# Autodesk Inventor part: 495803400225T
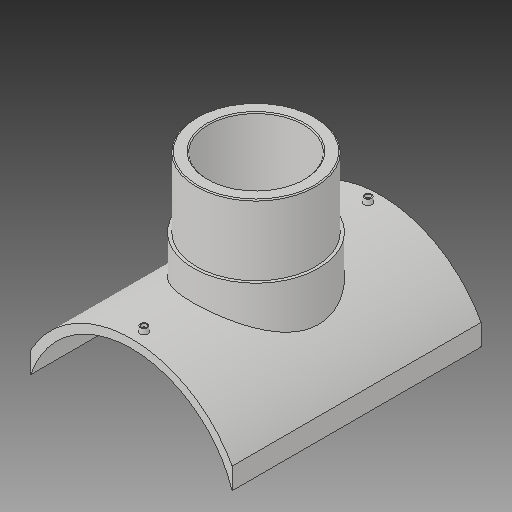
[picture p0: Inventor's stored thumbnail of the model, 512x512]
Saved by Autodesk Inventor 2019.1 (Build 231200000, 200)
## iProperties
Created: 2017-10
Part Number: 495803400225T
Material: Generic
Description: PLASSON BRANCH SADDLE  400x225
Document SubType Name: Modeling
Designer: KIM
Mass: 2754.05 g
Surface Area: 3037.44 cm^2
Volume: 2754.05 cm^3
Density: 1 g/cm^3
Appearance: Default
Author: KIM
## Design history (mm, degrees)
derived "495803.ipt"
feature "Solid1::495803.ipt"
tag "TaggingFeature1"
body "Solid1"
other parameters: "d1" = 16, "d4" = 0, "d12" = 225.6, "d13" = 14, "d14" = 211.5, "d16" = 5 deg, "d18" = 4, "d19" = 14, "d20" = 0, "d21" = 3, "d22" = 0, "d23" = 405, "d24" = 236.25, "d25" = 16, "d28" = 0, "d29" = 9.6, "d31" = 0, "d32" = 94.5, "d33" = 0, "d34" = 4, "d36" = 225, "d37" = 132.3, "d38" = 0, "d39" = 2, "d_1" = 225, "H_" = 189, "x_" = 16, "D_" = 16
